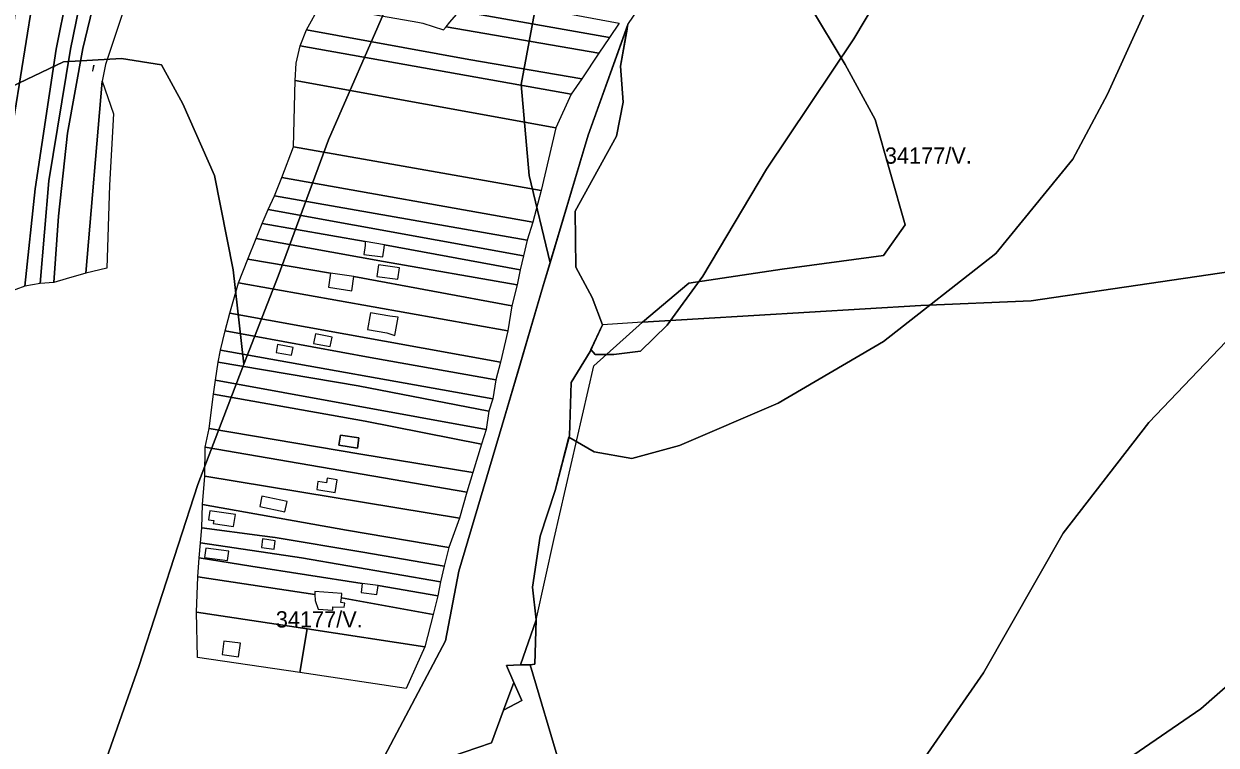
# Model space of a CAD drawing. Extents: x -532083 to -529270, y -1180561 to -1176456.
# Drawn here: x -531139.4 to -530772.6, y -1178980.2 to -1178758.4 of the extents above; entities that cross this region are included whole.
import ezdxf

# ---------------------------------------------------------------- set-up
doc = ezdxf.new("R2010")
doc.units = 0
for name, color, linetype in [('95560013', 7, 'Continuous'), ('95590013', 7, 'Continuous'), ('95610013', 7, 'Continuous'), ('95620013', 7, 'Continuous'), ('95660013', 7, 'Continuous')]:
    doc.layers.add(name, color=color, linetype=linetype)

msp = doc.modelspace()

# ---------------------------------------------------------------- linework, layer by layer
at = {"layer": '95560013'}
for points in [[(-531126.0803, -1178749.18145), (-531116.3133, -1178702.36245), (-531101.1023, -1178640.77545), (-531089.2103, -1178590.00745), (-531085.8813, -1178568.37645), (-531081.7723, -1178546.24845), (-531079.5113, -1178504.73645), (-531075.8933, -1178503.82945), (-531077.1773, -1178545.67545), (-531084.5083, -1178590.00745), (-531098.6133, -1178651.31745), (-531114.2693, -1178715.03345), (-531117.9753, -1178731.52645), (-531125.0213, -1178766.13645), (-531131.6493, -1178806.63945), (-531134.3683, -1178838.24945), (-531139.0493, -1178839.01345), (-531135.9443, -1178809.10145), (-531129.4393, -1178766.13645)], [(-531114.2693, -1178715.03345), (-531098.6133, -1178651.31745), (-531084.5083, -1178590.00745), (-531077.1773, -1178545.67545), (-531075.8933, -1178503.82945), (-531071.1443, -1178502.92245), (-531073.0423, -1178539.78245), (-531076.0893, -1178563.57445), (-531079.8063, -1178590.28545), (-531090.8693, -1178639.38845), (-531108.7113, -1178714.10445), (-531121.2173, -1178765.89045), (-531126.0033, -1178791.98945), (-531128.7033, -1178817.47245), (-531130.1113, -1178837.90245), (-531134.3683, -1178838.24945), (-531131.6493, -1178806.63945), (-531125.0213, -1178766.13645), (-531117.9753, -1178731.52645)], [(-531148.5443, -1178829.55845), (-531143.9133, -1178796.33845), (-531136.9653, -1178752.89845), (-531130.9443, -1178750.57545), (-531126.0803, -1178749.18145), (-531129.4393, -1178766.13645), (-531135.9443, -1178809.10145), (-531139.0493, -1178839.01345), (-531150.2283, -1178843.15745)]]:
    msp.add_lwpolyline(points, close=True, dxfattribs=at)
msp.add_lwpolyline([(-530974.5343, -1178986.22345), (-530983.6223, -1178955.52445), (-530982.2063, -1178955.29745), (-530981.8163, -1178941.61045), (-530976.1873, -1178916.67345), (-530964.0023, -1178863.53645), (-530949.0293, -1178850.10345), (-530863.4053, -1178845.00045), (-530829.5283, -1178843.57645), (-530753.4283, -1178832.35745)], dxfattribs=at)
at = {"layer": '95590013'}
for points in [[(-531079.8063, -1178590.28545), (-531076.0893, -1178563.57445), (-531073.0423, -1178539.78245), (-531071.1443, -1178502.92245), (-531065.9423, -1178501.78745), (-531067.6023, -1178535.41745), (-531070.6493, -1178562.26445), (-531074.8283, -1178590.28545), (-531088.1033, -1178648.82045), (-531102.7613, -1178710.96245), (-531112.8433, -1178754.52645), (-531106.5923, -1178747.73345), (-531114.2323, -1178770.89945), (-531115.2743, -1178775.95045), (-531120.3323, -1178835.01745), (-531126.3153, -1178836.74845), (-531130.1113, -1178837.90245), (-531128.7033, -1178817.47245), (-531126.0033, -1178791.98945), (-531121.2173, -1178765.89045), (-531108.7113, -1178714.10445), (-531090.8693, -1178639.38845)], [(-531002.5103, -1178769.36045), (-531052.3953, -1178760.14445), (-531048.1863, -1178752.58345), (-531018.1613, -1178757.82045), (-531016.6383, -1178758.17345), (-531010.3073, -1178760.21445), (-531009.4673, -1178759.23945), (-530962.5353, -1178767.33545), (-530967.6793, -1178775.28445)], [(-530962.5353, -1178767.33545), (-531009.4673, -1178759.23945), (-531008.2873, -1178757.86845), (-531004.8293, -1178753.85145), (-531003.9163, -1178754.63845), (-530959.2563, -1178762.51945)], [(-530959.2563, -1178762.51945), (-531003.9163, -1178754.63845), (-531000.9333, -1178751.17445), (-530979.9843, -1178753.70945), (-530956.2123, -1178758.17345)], [(-530971.0113, -1178779.99345), (-531054.3533, -1178765.15345), (-531052.3953, -1178760.14445), (-531002.5103, -1178769.36045), (-530967.6793, -1178775.28445)], [(-530975.7063, -1178790.32345), (-531055.8723, -1178775.76545), (-531055.6113, -1178770.39645), (-531054.3533, -1178765.15345), (-530971.0113, -1178779.99345)], [(-531118.2263, -1178772.81545), (-531118.1133, -1178772.93545), (-531117.8793, -1178771.07345)], [(-531120.3323, -1178835.01745), (-531115.2743, -1178775.95045), (-531111.8013, -1178786.05245), (-531112.9943, -1178807.99345), (-531113.8903, -1178833.51745)], [(-530980.2493, -1178809.61445), (-531056.3943, -1178796.19445), (-531055.8723, -1178775.76545), (-530975.7063, -1178790.32345)], [(-530982.8233, -1178819.33645), (-531060.0503, -1178805.62345), (-531056.3943, -1178796.19445), (-530980.2493, -1178809.61445)], [(-530984.5523, -1178824.84945), (-531062.2693, -1178811.25445), (-531060.0503, -1178805.62345), (-530982.8233, -1178819.33645)], [(-530985.6833, -1178829.72745), (-531064.2283, -1178815.44545), (-531062.2693, -1178811.25445), (-530984.5523, -1178824.84945)], [(-530986.7013, -1178834.03845), (-531028.4323, -1178826.32445), (-531034.4263, -1178825.30345), (-531066.0553, -1178819.76645), (-531064.2283, -1178815.44545), (-530985.6833, -1178829.72745)], [(-530987.6053, -1178838.57645), (-531028.7723, -1178831.42945), (-531067.8833, -1178824.35045), (-531066.0553, -1178819.76645), (-531034.4263, -1178825.30345), (-531034.3943, -1178826.50845), (-531034.7653, -1178829.27645), (-531028.9333, -1178830.05645), (-531028.5633, -1178827.28845), (-531028.4323, -1178826.32445), (-530986.7013, -1178834.03845)], [(-531045.0463, -1178835.00945), (-531070.5033, -1178830.74845), (-531067.8833, -1178824.35045), (-531028.7723, -1178831.42945), (-530987.6053, -1178838.57645), (-530989.3023, -1178845.04245), (-531037.8153, -1178836.10145)], [(-530990.5123, -1178852.78245), (-531073.3233, -1178838.02945), (-531070.5033, -1178830.74845), (-531045.0463, -1178835.00945), (-531045.7023, -1178839.34845), (-531038.4713, -1178840.44045), (-531037.8153, -1178836.10145), (-530989.3023, -1178845.04245)], [(-531030.7463, -1178836.06845), (-531024.2933, -1178836.92645), (-531023.8203, -1178833.37145), (-531030.2733, -1178832.51345)], [(-530992.7503, -1178862.40445), (-531076.0403, -1178847.33045), (-531073.3233, -1178838.02945), (-530990.5123, -1178852.78245)], [(-531032.8773, -1178860.96145), (-531077.4793, -1178852.78245), (-531076.0403, -1178847.33045), (-530992.7503, -1178862.40445), (-530994.1893, -1178867.85645)], [(-531025.2033, -1178854.22545), (-531024.2443, -1178848.61345), (-531026.7753, -1178848.26745), (-531032.7353, -1178847.18745), (-531033.6683, -1178852.33445), (-531027.7083, -1178853.41445)], [(-530995.0763, -1178873.66045), (-531078.9003, -1178858.75645), (-531077.4793, -1178852.78245), (-531032.8773, -1178860.96145), (-530994.1893, -1178867.85645)], [(-531050.2563, -1178856.61245), (-531045.1243, -1178857.62645), (-531044.5433, -1178854.68445), (-531049.6743, -1178853.67045)], [(-531036.5683, -1178869.72345), (-531079.6013, -1178862.41145), (-531078.9003, -1178858.75645), (-530995.0763, -1178873.66045), (-530996.3383, -1178877.45645)], [(-531061.7363, -1178859.43145), (-531056.9933, -1178860.28945), (-531056.5543, -1178857.86045), (-531061.2963, -1178857.00245)], [(-530997.1793, -1178883.08045), (-531080.4423, -1178867.89545), (-531079.6013, -1178862.41145), (-531036.5683, -1178869.72345), (-530996.3383, -1178877.45645)], [(-531034.3253, -1178880.54945), (-531081.0033, -1178872.25445), (-531080.4423, -1178867.89545), (-530997.1793, -1178883.08045), (-530998.5813, -1178887.58045)], [(-531035.7273, -1178890.67345), (-531082.4043, -1178882.79945), (-531081.0033, -1178872.25445), (-531034.3253, -1178880.54945), (-530998.5813, -1178887.58045), (-531001.2443, -1178896.29745)], [(-531003.0893, -1178902.34145), (-531083.5793, -1178888.56545), (-531082.4043, -1178882.79945), (-531035.7273, -1178890.67345), (-531001.2443, -1178896.29745)], [(-531036.7793, -1178888.81445), (-531036.2833, -1178885.71545), (-531041.9363, -1178884.81145), (-531042.4323, -1178887.90945)], [(-531036.7793, -1178888.81445), (-531042.4323, -1178887.90945), (-531041.9363, -1178884.81145), (-531036.2833, -1178885.71545)], [(-531005.3493, -1178910.36345), (-531083.7533, -1178897.45945), (-531083.5793, -1178888.56545), (-531003.0893, -1178902.34145)], [(-531040.1183, -1178914.02545), (-531084.4483, -1178906.17845), (-531083.7533, -1178897.45945), (-531005.3493, -1178910.36345), (-531008.6523, -1178919.43145)], [(-531048.8903, -1178899.08845), (-531049.2883, -1178901.60245), (-531043.5753, -1178902.50745), (-531042.9603, -1178898.62345), (-531046.0673, -1178898.13145), (-531046.2843, -1178899.50045)], [(-531058.3873, -1178905.25145), (-531066.1163, -1178903.59745), (-531066.7933, -1178906.76045), (-531059.0643, -1178908.41445)], [(-531035.0763, -1178920.82645), (-531062.0223, -1178916.29245), (-531066.0213, -1178915.76945), (-531084.6223, -1178913.32745), (-531084.4483, -1178906.17845), (-531040.1183, -1178914.02545), (-531008.6523, -1178919.43145), (-531010.0433, -1178925.18545)], [(-531080.9693, -1178911.12345), (-531081.0963, -1178911.99445), (-531074.8483, -1178912.90145), (-531074.3163, -1178909.24145), (-531082.1493, -1178908.10445), (-531082.5543, -1178910.89345)], [(-531053.9643, -1178922.57245), (-531085.0203, -1178917.98745), (-531084.6223, -1178913.32745), (-531066.0213, -1178915.76945), (-531062.0223, -1178916.29245), (-531035.0763, -1178920.82645), (-531010.0433, -1178925.18545), (-531011.2423, -1178930.00545)], [(-531035.2583, -1178930.43245), (-531069.5703, -1178925.10245), (-531085.4933, -1178922.57245), (-531085.0203, -1178917.98745), (-531053.9643, -1178922.57245), (-531011.2423, -1178930.00545), (-531012.0303, -1178934.27445), (-531030.4153, -1178931.05245)], [(-531065.9693, -1178916.78745), (-531066.3163, -1178919.42145), (-531062.4003, -1178919.93745), (-531062.0533, -1178917.30445)], [(-531041.5453, -1178933.53345), (-531049.8893, -1178932.97145), (-531049.8923, -1178933.84445), (-531085.8083, -1178928.42345), (-531085.4933, -1178922.57245), (-531069.5703, -1178925.10245), (-531035.2583, -1178930.43245), (-531035.6163, -1178933.23045), (-531030.7733, -1178933.85045), (-531030.4153, -1178931.05245), (-531012.0303, -1178934.27445), (-531013.4493, -1178939.96745), (-531041.6483, -1178934.87745)], [(-531083.4223, -1178919.60045), (-531083.7983, -1178922.47245), (-531076.6873, -1178923.40345), (-531076.3113, -1178920.53145)], [(-531015.9713, -1178949.92945), (-531052.2303, -1178944.39445), (-531086.2813, -1178939.33445), (-531085.8083, -1178928.42345), (-531049.8923, -1178933.84445), (-531049.7833, -1178935.73145), (-531048.8843, -1178938.38445), (-531044.3333, -1178938.65045), (-531044.3333, -1178937.69445), (-531040.7883, -1178937.80045), (-531040.6293, -1178936.47445), (-531041.8463, -1178936.36845), (-531041.6483, -1178934.87745), (-531013.4493, -1178939.96745)], [(-531054.4373, -1178957.83545), (-531085.9663, -1178953.25045), (-531086.2813, -1178939.33445), (-531052.2303, -1178944.39445)], [(-531021.8043, -1178962.73745), (-531054.4373, -1178957.83545), (-531052.2303, -1178944.39445), (-531015.9713, -1178949.92945)], [(-531077.8593, -1178948.17545), (-531078.3813, -1178952.34245), (-531073.3023, -1178952.97945), (-531072.7793, -1178948.81245)]]:
    msp.add_lwpolyline(points, close=True, dxfattribs=at)
msp.add_lwpolyline([(-531143.3673, -1178767.76145), (-531137.2273, -1178711.43445), (-531129.5003, -1178679.88945), (-531119.2563, -1178644.91845), (-531117.4553, -1178623.21045), (-531111.4003, -1178611.77845), (-531108.9063, -1178606.89545), (-531109.5003, -1178603.44145), (-531110.6873, -1178596.41545), (-531110.5683, -1178593.08045), (-531108.3133, -1178577.24145), (-531100.9953, -1178560.31245), (-531091.7233, -1178543.75345), (-531093.4973, -1178561.17345), (-531098.8903, -1178589.17545), (-531109.9523, -1178631.62045), (-531122.1213, -1178679.33645), (-531128.2063, -1178705.96845), (-531136.9653, -1178752.89845), (-531143.9133, -1178796.33845)], dxfattribs=at)
at = {"layer": '95610013'}
for points in [[(-530753.4283, -1178832.35745), (-530829.5283, -1178843.57645), (-530863.4053, -1178845.00045), (-530949.0293, -1178850.10345), (-530934.7623, -1178838.12245), (-530906.0623, -1178833.79545), (-530874.8743, -1178829.63545), (-530868.2383, -1178820.15045), (-530877.5263, -1178787.75445), (-530886.7353, -1178770.90145), (-530897.7213, -1178752.58845), (-530900.7903, -1178726.01145), (-530891.5813, -1178714.01945), (-530871.3873, -1178714.01945), (-530864.9643, -1178714.63945), (-530823.3393, -1178718.17045), (-530821.8903, -1178701.13745), (-530774.0523, -1178700.92945), (-530705.5063, -1178701.13745)], [(-530897.7213, -1178752.58845), (-530886.7353, -1178770.90145), (-530877.5263, -1178787.75445), (-530868.2383, -1178820.15045), (-530874.8743, -1178829.63545), (-530906.0623, -1178833.79545), (-530934.7623, -1178838.12245), (-530949.0293, -1178850.10345), (-530961.3893, -1178850.92245), (-530964.5853, -1178842.47145), (-530969.5243, -1178833.14545), (-530969.8153, -1178815.95145), (-530957.0313, -1178792.92845), (-530954.9973, -1178782.43645), (-530955.8693, -1178771.36245), (-530953.5453, -1178758.53945), (-530936.8713, -1178733.81145)]]:
    msp.add_lwpolyline(points, dxfattribs=at)
msp.add_lwpolyline([(-530986.5903, -1178983.24645), (-530998.2743, -1178986.03745), (-531009.0323, -1178988.45645), (-531008.1043, -1178983.80445), (-530995.4923, -1178979.52545), (-530991.7833, -1178969.47845), (-530986.2193, -1178966.50145), (-530988.6303, -1178960.91945), (-530990.8563, -1178955.71045), (-530986.5903, -1178955.52445), (-530983.6223, -1178955.52445), (-530974.5343, -1178986.22345), (-530950.6093, -1179017.85245), (-530955.1983, -1179018.79845), (-531015.3193, -1179028.70645), (-531012.5273, -1179020.95245), (-530996.7913, -1179018.03845), (-530998.0893, -1179007.43345), (-530985.4773, -1179005.38745), (-530986.5903, -1178995.34045), (-530984.9213, -1178994.78145)], close=True, dxfattribs=at)
at = {"layer": '95620013'}
msp.add_lwpolyline([(-531029.3253, -1178985.34245), (-531009.6953, -1178948.12645), (-531005.5503, -1178926.69545), (-530992.1863, -1178881.81545), (-530979.6933, -1178839.26645), (-530965.7473, -1178792.63645), (-530953.5453, -1178758.53945), (-530955.8693, -1178771.36245), (-530954.9973, -1178782.43645), (-530957.0313, -1178792.92845), (-530969.8153, -1178815.95145), (-530969.5243, -1178833.14545), (-530964.5853, -1178842.47145), (-530961.3893, -1178850.92245), (-530965.1663, -1178859.08245), (-530970.9773, -1178868.69945), (-530971.5583, -1178885.01945), (-530975.9163, -1178901.92345), (-530980.5643, -1178915.91245), (-530982.8893, -1178931.64945), (-530981.8163, -1178941.61045), (-530982.2063, -1178955.29745), (-530983.6223, -1178955.52445), (-530986.5903, -1178955.52445), (-530990.8563, -1178955.71045), (-530988.6303, -1178960.91945), (-530986.2193, -1178966.50145), (-530991.7833, -1178969.47845), (-530995.4923, -1178979.52545), (-531008.1043, -1178983.80445)], dxfattribs=at)
at = {"layer": '95660013'}
for points in [[(-531131.1253, -1179033.00045), (-531104.0003, -1178956.00045), (-531085.8753, -1178900.00045), (-531071.6873, -1178863.00045), (-531061.1253, -1178836.00045), (-531045.6253, -1178794.00045), (-531027.3123, -1178752.00045), (-531006.8123, -1178730.00045), (-530989.6873, -1178707.00045), (-530983.1253, -1178703.00045), (-530977.3753, -1178709.00045), (-530976.6253, -1178720.00045), (-530982.3123, -1178755.00045), (-530986.3753, -1178777.00045), (-530983.8753, -1178805.00045), (-530977.4713, -1178831.83645), (-530979.6933, -1178839.26645), (-530987.3013, -1178865.17945), (-530992.1863, -1178881.81545), (-531005.5503, -1178926.69545), (-531009.6953, -1178948.12645), (-531029.3253, -1178985.34245)], [(-530860.8123, -1178724.00045), (-530884.0003, -1178763.00045), (-530910.8753, -1178803.00045), (-530930.5003, -1178836.00045), (-530941.5003, -1178851.00045), (-530949.6873, -1178859.00045), (-530957.8753, -1178860.00045), (-530963.6253, -1178860.00045), (-530964.9173, -1178858.54345), (-530961.3893, -1178850.92245), (-530964.5853, -1178842.47145), (-530969.5243, -1178833.14545), (-530969.8153, -1178815.95145), (-530957.0313, -1178792.92845), (-530954.9973, -1178782.43645), (-530955.8693, -1178771.36245), (-530953.8033, -1178759.96445), (-530954.3173, -1178760.69845), (-530965.7473, -1178792.63645), (-530977.4713, -1178831.83645), (-530983.8753, -1178805.00045), (-530986.3753, -1178777.00045), (-530982.3123, -1178755.00045)], [(-530788.8123, -1178742.00045), (-530806.0003, -1178780.00045), (-530816.6873, -1178800.00045), (-530840.3753, -1178829.00045), (-530874.8753, -1178856.00045), (-530907.3123, -1178875.00045), (-530937.6253, -1178888.00045), (-530952.3753, -1178892.00045), (-530963.8753, -1178890.00045), (-530971.6863, -1178885.51745), (-530971.5583, -1178885.01945), (-530970.9773, -1178868.69945), (-530965.1663, -1178859.08245), (-530964.9173, -1178858.54345), (-530963.6253, -1178860.00045), (-530957.8753, -1178860.00045), (-530949.6873, -1178859.00045), (-530941.5003, -1178851.00045), (-530930.5003, -1178836.00045), (-530910.8753, -1178803.00045), (-530884.0003, -1178763.00045), (-530860.8123, -1178724.00045)], [(-531008.1043, -1178983.80445), (-530995.4923, -1178979.52545), (-530991.7833, -1178969.47845), (-530988.6303, -1178960.91945), (-530990.8563, -1178955.71045), (-530986.5903, -1178955.52445), (-530981.8163, -1178941.61045), (-530982.8893, -1178931.64945), (-530980.5643, -1178915.91245), (-530975.9163, -1178901.92345), (-530971.6863, -1178885.51745), (-530963.8753, -1178890.00045), (-530952.3753, -1178892.00045), (-530937.6253, -1178888.00045), (-530907.3123, -1178875.00045), (-530874.8753, -1178856.00045), (-530840.3753, -1178829.00045), (-530816.6873, -1178800.00045), (-530806.0003, -1178780.00045), (-530788.8123, -1178742.00045)], [(-531027.3123, -1178752.00045), (-531045.6253, -1178794.00045), (-531061.1253, -1178836.00045), (-531071.6873, -1178863.00045), (-531075.0003, -1178834.00045), (-531080.6873, -1178805.00045), (-531090.5003, -1178783.00045), (-531097.0003, -1178771.00045), (-531109.3123, -1178769.00045), (-531127.1873, -1178770.00045), (-531145.4433, -1178778.73445)], [(-531029.3253, -1178985.34245), (-531009.6953, -1178948.12645), (-531005.5503, -1178926.69545), (-530992.1863, -1178881.81545), (-530987.3013, -1178865.17945), (-530979.6933, -1178839.26645), (-530977.4713, -1178831.83645), (-530965.7473, -1178792.63645), (-530954.3173, -1178760.69845), (-530953.8033, -1178759.96445), (-530955.8693, -1178771.36245), (-530954.9973, -1178782.43645), (-530957.0313, -1178792.92845), (-530969.8153, -1178815.95145), (-530969.5243, -1178833.14545), (-530964.5853, -1178842.47145), (-530961.3893, -1178850.92245), (-530964.9173, -1178858.54345), (-530965.1663, -1178859.08245), (-530970.9773, -1178868.69945), (-530971.5583, -1178885.01945), (-530971.6863, -1178885.51745), (-530975.9163, -1178901.92345), (-530980.5643, -1178915.91245), (-530982.8893, -1178931.64945), (-530981.8163, -1178941.61045), (-530986.5903, -1178955.52445), (-530990.8563, -1178955.71045), (-530988.6303, -1178960.91945), (-530991.7833, -1178969.47845), (-530995.4923, -1178979.52545), (-531008.1043, -1178983.80445)], [(-531145.4433, -1178778.73445), (-531127.1873, -1178770.00045), (-531109.3123, -1178769.00045), (-531097.0003, -1178771.00045), (-531090.5003, -1178783.00045), (-531080.6873, -1178805.00045), (-531075.0003, -1178834.00045), (-531071.6873, -1178863.00045), (-531085.8753, -1178900.00045), (-531104.0003, -1178956.00045), (-531131.1253, -1179033.00045)], [(-530889.3123, -1179023.00045), (-530844.1253, -1178958.00045), (-530819.6253, -1178915.00045), (-530793.3123, -1178881.00045), (-530769.5003, -1178856.00045)], [(-530769.5003, -1178856.00045), (-530793.3123, -1178881.00045), (-530819.6253, -1178915.00045), (-530844.1253, -1178958.00045), (-530889.3123, -1179023.00045)], [(-530705.8753, -1178982.00045), (-530680.6253, -1178959.00045), (-530664.8753, -1178943.00045), (-530655.8753, -1178927.00045), (-530655.8753, -1178911.00045), (-530659.1873, -1178902.00045), (-530672.3123, -1178895.00045), (-530685.3753, -1178896.00045), (-530693.6873, -1178898.00045), (-530711.6873, -1178910.00045), (-530739.6253, -1178936.00045), (-530777.3123, -1178969.00045), (-530822.3753, -1179000.00045)], [(-530822.3753, -1179000.00045), (-530777.3123, -1178969.00045), (-530739.6253, -1178936.00045), (-530711.6873, -1178910.00045), (-530693.6873, -1178898.00045), (-530685.3753, -1178896.00045), (-530672.3123, -1178895.00045), (-530659.1873, -1178902.00045), (-530655.8753, -1178911.00045), (-530655.8753, -1178927.00045), (-530664.8753, -1178943.00045), (-530680.6253, -1178959.00045), (-530705.8753, -1178982.00045)]]:
    msp.add_lwpolyline(points, dxfattribs=at)

# ---------------------------------------------------------------- texts
for rotation, p in [(0, (-530874.4993, -1178801.36343)), (360, (-531061.8753, -1178944.00199))]:
    msp.add_text('34177/V.', height=5, rotation=rotation, dxfattribs=at).set_placement(p)

doc.saveas('drawing.dxf')
